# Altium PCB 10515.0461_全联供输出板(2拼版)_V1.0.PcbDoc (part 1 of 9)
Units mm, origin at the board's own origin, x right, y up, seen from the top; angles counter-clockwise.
Board outline 283.88 x 134.8 mm, 2 copper layers (Top Layer, Bottom Layer); 298 components, 0 nets, 1264 pads, 970 vias.
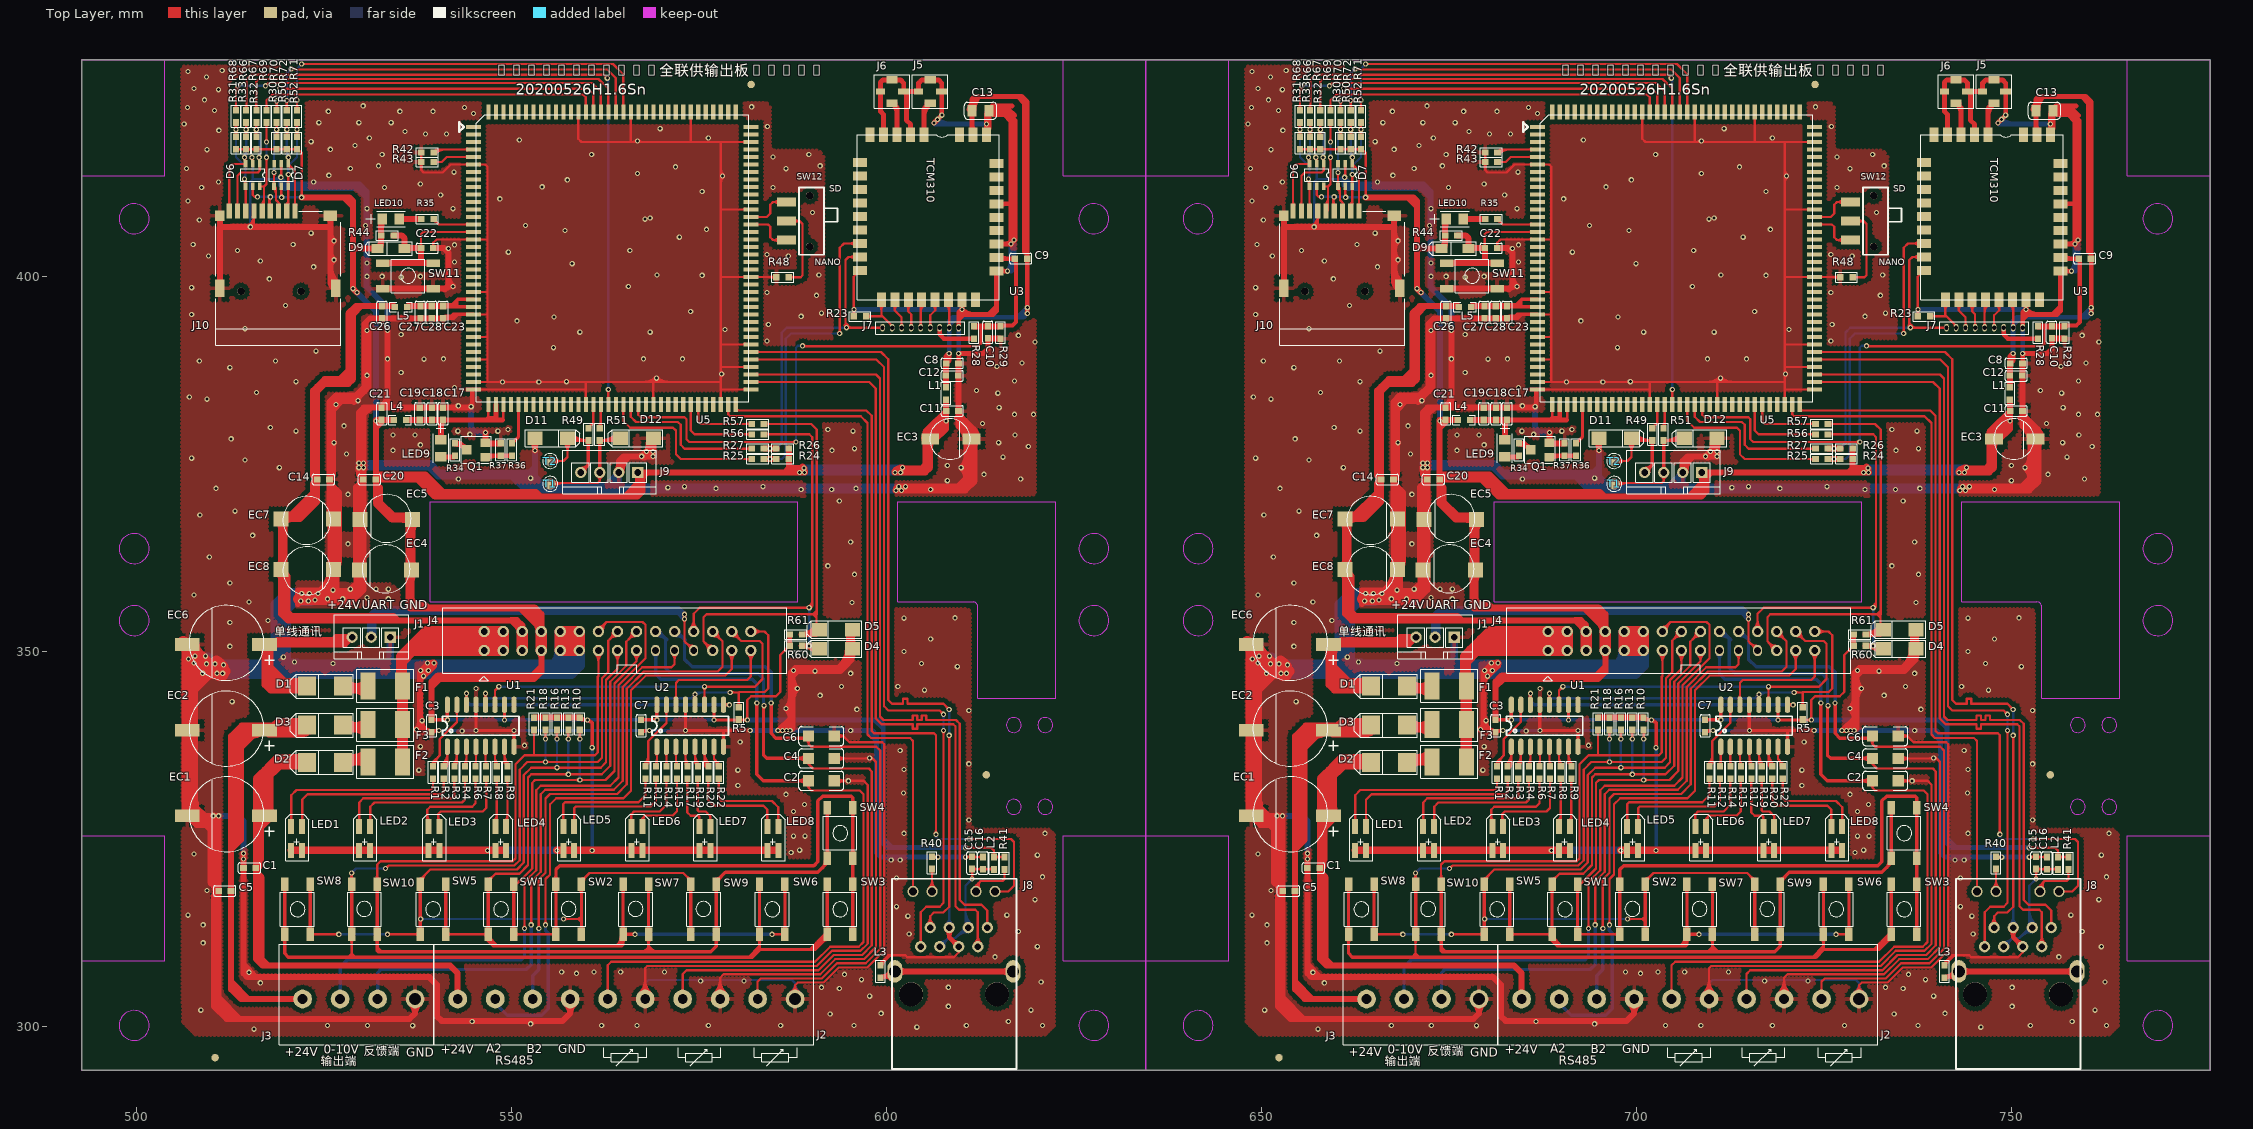
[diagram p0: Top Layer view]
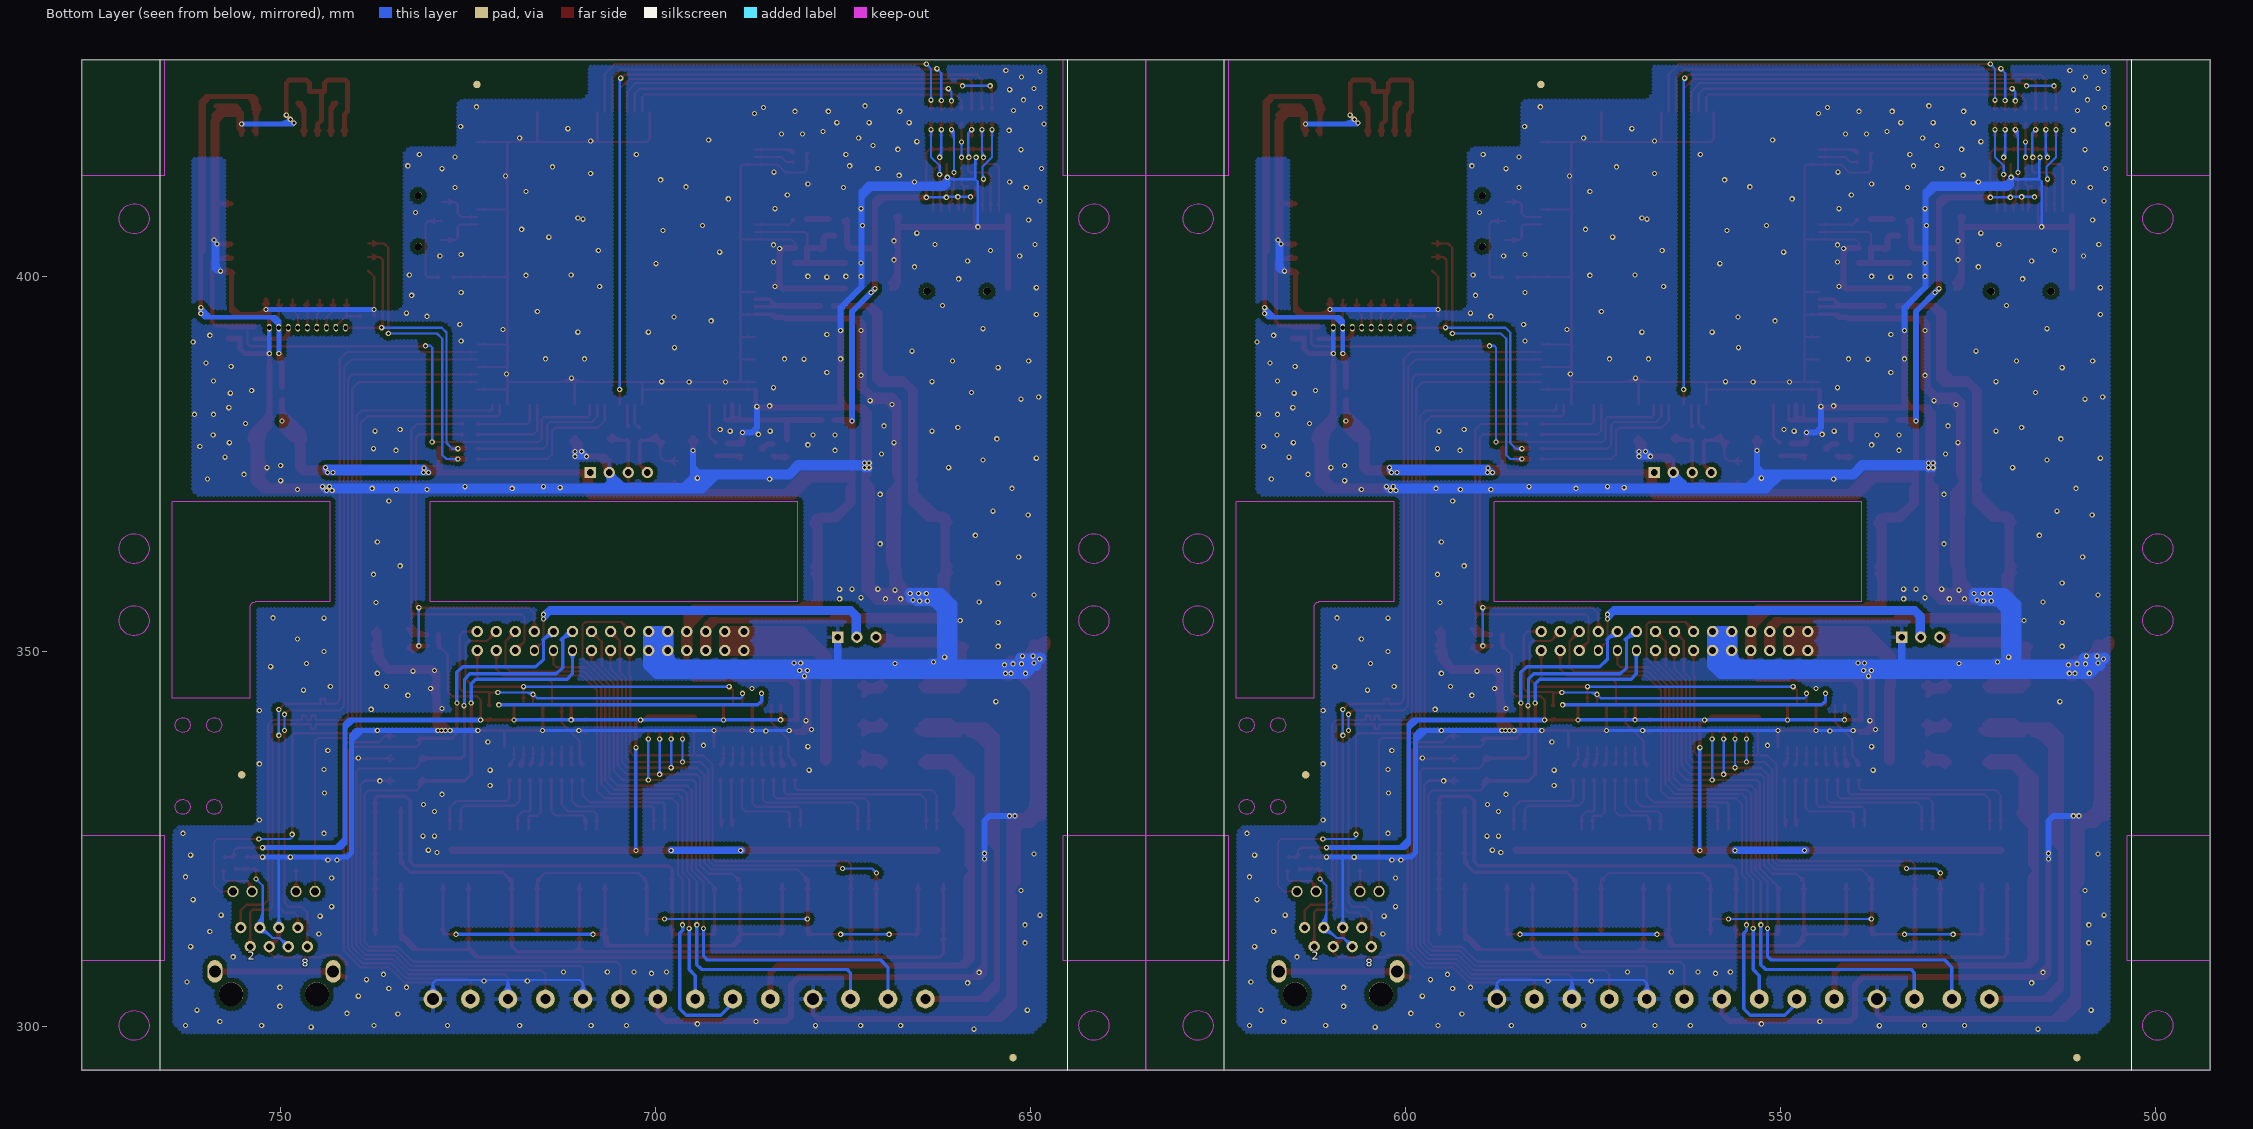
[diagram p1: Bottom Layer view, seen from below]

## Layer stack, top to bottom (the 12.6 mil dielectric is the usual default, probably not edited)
Top Layer: signal copper 0.0356
Dielectric: dielectric 0.32, FR-4, Dk 4.8
Bottom Layer: signal copper 0.0356

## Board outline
492.633,428.879 776.517,428.879 776.517,294.079 492.633,294.079 492.633,428.879

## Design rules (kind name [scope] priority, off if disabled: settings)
Clearance [All] p1: gap=0.254
PolygonConnect [All] p1: connectstyle=Relief reliefconductorwidth=0.254 reliefentries=4 polygonreliefangle="90 Angle"
RoutingVias [All] p1: holewidth=0.711 width=1.27 viastyle="Through Hole" minholewidth=0.711 minwidth=1.27 maxholewidth=0.711 maxwidth=1.27
SilkscreenOverComponentPads [All] p1: minsilkscreentomaskgap=0.254
SolderMaskExpansion [All] p1: expansion=0.102
Width [All] p1: maxlimit=0.254 minlimit=0.254 preferedwidth=0.254
27 further rules are at their usual default settings.

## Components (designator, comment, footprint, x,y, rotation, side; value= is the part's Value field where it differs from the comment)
C1 "0.1uF/0603" CAP/SMT/0603C 656.123,321.003 r0 top
C1 "0.1uF/0603" CAP/SMT/0603C 514.223,321.003 r0 top
C2 "1nF/1206" CAP/SMT/1206C 731.434,332.687 r0 top
C2 "1nF/1206" CAP/SMT/1206C 589.534,332.687 r0 top
C3 "0.1uF/0603" CAP/SMT/0603C 681.142,340.815 r270 top
C3 "0.1uF/0603" CAP/SMT/0603C 539.242,340.815 r270 top
C4 "1nF/1206" CAP/SMT/1206C 731.434,335.672 r0 top
C4 "1nF/1206" CAP/SMT/1206C 589.534,335.672 r0 top
C5 "0.1uF/0603" CAP/SMT/0603C 652.821,317.955 r0 top
C5 "0.1uF/0603" CAP/SMT/0603C 510.921,317.955 r0 top
C6 "1nF/1206" CAP/SMT/1206C 731.434,338.656 r0 top
C6 "1nF/1206" CAP/SMT/1206C 589.534,338.656 r0 top
C7 "0.1uF/0603" CAP/SMT/0603C 709.082,340.815 r270 top
C7 "0.1uF/0603" CAP/SMT/0603C 567.182,340.815 r270 top
C8 "10uF/0603" CAP/SMT/0603C 749.849,388.313 r0 top
C8 "10uF/0603" CAP/SMT/0603C 607.949,388.313 r0 top
C9 "0.1uF/0603" CAP/SMT/0603C 758.993,402.283 r0 top
C9 "0.1uF/0603" CAP/SMT/0603C 617.093,402.283 r0 top
C10 "0.1uF/0603" CAP/SMT/0603C 755.437,391.742 r90 top
C10 "0.1uF/0603" CAP/SMT/0603C 613.537,391.742 r90 top
C11 "0.1uF/0603" CAP/SMT/0603C 749.849,381.963 r0 top
C11 "0.1uF/0603" CAP/SMT/0603C 607.949,381.963 r0 top
C12 "0.1uF/0603" CAP/SMT/0603C 751.404,386.789 r180 top
C12 "0.1uF/0603" CAP/SMT/0603C 609.504,386.789 r180 top
C13 "22uF/0805" CAP/SMT/0805C 755.564,422.095 r180 top
C13 "22uF/0805" CAP/SMT/0805C 613.664,422.095 r180 top
C14 "0.1uF/0603" CAP/SMT/0603C 667.553,372.969 r180 top
C14 "0.1uF/0603" CAP/SMT/0603C 525.653,372.969 r180 top
C15 "0.1uF/0603" CAP/SMT/0603C 753.336,320.963 r90 top
C15 "0.1uF/0603" CAP/SMT/0603C 611.436,320.963 r90 top
C16 "10uF/0603" CAP/SMT/0603C 754.675,322.517 r270 top
C16 "10uF/0603" CAP/SMT/0603C 612.775,322.517 r270 top
C17 "1uF/0603" CAP/SMT/0603C 682.666,382.446 r270 top
C17 "1uF/0603" CAP/SMT/0603C 540.766,382.446 r270 top
C18 "0.1uF/0603" CAP/SMT/0603C 681.18,382.446 r270 top
C18 "0.1uF/0603" CAP/SMT/0603C 539.28,382.446 r270 top
C19 "0.1uF/0603" CAP/SMT/0603C 679.568,382.446 r270 top
C19 "0.1uF/0603" CAP/SMT/0603C 537.668,382.446 r270 top
C20 "1uF/0603" CAP/SMT/0603C 672.125,372.819 r0 top
C20 "1uF/0603" CAP/SMT/0603C 530.225,372.819 r0 top
C21 "0.1uF/0603" CAP/SMT/0603C 674.488,382.446 r270 top
C21 "0.1uF/0603" CAP/SMT/0603C 532.588,382.446 r270 top
C22 "0.1uF/0603" CAP/SMT/0603C 681.396,403.807 r180 top
C22 "0.1uF/0603" CAP/SMT/0603C 539.496,403.807 r180 top
C23 "0.1uF/0603" CAP/SMT/0603C 682.793,394.409 r90 top
C23 "0.1uF/0603" CAP/SMT/0603C 540.893,394.409 r90 top
C26 "0.1uF/0603" CAP/SMT/0603C 674.665,394.409 r90 top
C26 "0.1uF/0603" CAP/SMT/0603C 532.765,394.409 r90 top
C27 "0.1uF/0603" CAP/SMT/0603C 679.745,394.409 r90 top
C27 "0.1uF/0603" CAP/SMT/0603C 537.845,394.409 r90 top
C28 "0.1uF/0603" CAP/SMT/0603C 681.269,394.409 r90 top
C28 "0.1uF/0603" CAP/SMT/0603C 539.369,394.409 r90 top
D1 "1N5819" D/SMT/DO-214AC 669.331,345.387 r0 top
D1 "1N5819" D/SMT/DO-214AC 527.431,345.387 r0 top
D2 "1N5819" D/SMT/DO-214AC 669.331,335.227 r0 top
D2 "1N5819" D/SMT/DO-214AC 527.431,335.227 r0 top
D3 "1N5819" D/SMT/DO-214AC 669.331,340.18 r0 top
D3 "1N5819" D/SMT/DO-214AC 527.431,340.18 r0 top
D4 "SMF6.5CA/SOD-123" D/SMT/SOD123 732.704,350.34 r0 top
D4 "SMF6.5CA/SOD-123" D/SMT/SOD123 590.804,350.34 r0 top
D5 "SMF6.5CA/SOD-123" D/SMT/SOD123 732.704,352.88 r0 top
D5 "SMF6.5CA/SOD-123" D/SMT/SOD123 590.804,352.88 r0 top
D6 "SR05-4B/SOT-363" TSOT-6L 658.282,414.983 r270 top
D6 "SR05-4B/SOT-363" TSOT-6L 516.382,414.983 r270 top
D7 "SR05-4B/SOT-363" TSOT-6L 662.092,414.983 r270 top
D7 "SR05-4B/SOT-363" TSOT-6L 520.192,414.983 r270 top
D9 "1N4148/SOD-123" D/SMT/SOD-123 675.808,403.68 r0 top
D9 "1N4148/SOD-123" D/SMT/SOD-123 533.908,403.68 r0 top
D11 "SMF6.5CA/SOD-123" D/SMT/SOD123 699.557,378.407 r180 top
D11 "SMF6.5CA/SOD-123" D/SMT/SOD123 557.657,378.407 r180 top
D12 "SMF6.5CA/SOD-123" D/SMT/SOD123 706.161,378.407 r0 top
D12 "SMF6.5CA/SOD-123" D/SMT/SOD123 564.261,378.407 r0 top
EC1 "220uF/50V" CAP/SMT/220UF/50V 658.917,323.035 r180 top
EC1 "220uF/50V" CAP/SMT/220UF/50V 517.017,323.035 r180 top
EC2 "220uF/50V" CAP/SMT/220UF/50V 658.917,334.465 r180 top
EC2 "220uF/50V" CAP/SMT/220UF/50V 517.017,334.465 r180 top
EC3 "47uF/16V" CAP/SMT/47uF/16V 747.69,378.28 r0 top
EC3 "47uF/16V" CAP/SMT/47uF/16V 605.79,378.28 r0 top
EC4 "100uF/25V" CAP/SMT/100UF/25V 678.221,360.677 r180 top
EC4 "100uF/25V" CAP/SMT/100UF/25V 536.321,360.677 r180 top
EC5 "100uF/25V" CAP/SMT/100UF/25V 678.348,367.408 r180 top
EC5 "100uF/25V" CAP/SMT/100UF/25V 536.448,367.408 r180 top
EC6 "220uF/50V" CAP/SMT/220UF/50V 658.917,345.895 r180 top
EC6 "220uF/50V" CAP/SMT/220UF/50V 517.017,345.895 r180 top
EC7 "100uF/25V" CAP/SMT/100UF/25V 661.457,367.739 r0 top
EC7 "100uF/25V" CAP/SMT/100UF/25V 519.557,367.739 r0 top
EC8 "100uF/25V" CAP/SMT/100UF/25V 661.457,361.008 r0 top
EC8 "100uF/25V" CAP/SMT/100UF/25V 519.557,361.008 r0 top
F1 "500MA" FUSE/100MA/SMC 677.332,345.387 r180 top
F1 "500MA" FUSE/100MA/SMC 535.432,345.387 r180 top
F2 "500MA" FUSE/100MA/SMC 672.665,335.227 r0 top
F2 "500MA" FUSE/100MA/SMC 530.765,335.227 r0 top
F3 "500MA" FUSE/100MA/SMC 672.665,340.18 r0 top
F3 "500MA" FUSE/100MA/SMC 530.765,340.18 r0 top
J1 "CON/DIP/1X3PIN/2.54MM" CON/DIP/1×3PIN/2.54MM/插件端子 675.681,351.864 r270 top
J1 "CON/DIP/1X3PIN/2.54MM" CON/DIP/1×3PIN/2.54MM/插件端子 533.781,351.864 r270 top
J2 "WJ305-5.0" CON/DIP/1×10PIN/5.0MM/WJ103-10P 707.177,303.604 r180 top locked
J2 "WJ305-5.0" CON/DIP/1×10PIN/5.0MM/WJ103-10P 565.277,303.604 r180 top locked
J3 "WJ103-5.0" CON/DIP/1×4PIN/5.0MM/WJ103-4P 671.49,303.604 r180 top
J3 "WJ103-5.0" CON/DIP/1×4PIN/5.0MM/WJ103-4P 529.59,303.604 r180 top
J4 "CON/DIP/2X15PIN" CON/DIP/2X15PIN/2.54MM 688.206,350.086 r90 top
J4 "CON/DIP/2X15PIN" CON/DIP/2X15PIN/2.54MM 546.306,350.086 r90 top
J5 "NC" W.FL.LP-3MM 747.69,424.635 r270 top
J5 "NC" W.FL.LP-3MM 605.79,424.635 r270 top
J6 "Antena_W.FL-LP" W.FL.LP-3MM 742.61,424.635 r270 top
J6 "Antena_W.FL-LP" W.FL.LP-3MM 600.71,424.635 r270 top
J7 "CON/1X9PIN" CON/DIP/1×9PIN/1.27MM 751.5,393.139 r180 top
J7 "CON/1X9PIN" CON/DIP/1×9PIN/1.27MM 609.6,393.139 r180 top
J8 "MJ3A-B211-RSL15T022-1" RJ45-MJ3A-B211-RSL15T022-1 745.404,317.955 r0 top locked
J8 "MJ3A-B211-RSL15T022-1" RJ45-MJ3A-B211-RSL15T022-1 603.504,317.955 r0 top locked
J9 "1X4PIN/2.54MM" CON/DIP/1×4PIN/2.54MM/插件端子 708.701,373.835 r270 top
J9 "1X4PIN/2.54MM" CON/DIP/1×4PIN/2.54MM/插件端子 566.801,373.835 r270 top
J10 "OTHER/MicroSD" TF-01A 660.695,403.553 r0 top
J10 "OTHER/MicroSD" TF-01A 518.795,403.553 r0 top
L1 "10uH/0603/磁珠" 0603R 749.776,384.376 r90 top
L1 "10uH/0603/磁珠" 0603R 607.876,384.376 r90 top
L2 "220R/0603/磁珠" 0603R 756.199,321.715 r270 top
L2 "220R/0603/磁珠" 0603R 614.299,321.715 r270 top
L3 "10uH/0603/磁珠" 0603R 741.086,307.287 r270 top
L3 "10uH/0603/磁珠" 0603R 599.186,307.287 r270 top
L4 "L/10uH" L/SMT/0603L 676.189,380.878 r0 top
L4 "L/10uH" L/SMT/0603L 534.289,380.878 r0 top
L5 "L/10uH" L/SMT/0603L 676.316,395.933 r0 top
L5 "L/10uH" L/SMT/0603L 534.416,395.933 r0 top
LED1 "WEJT910C-R3H4共阳" D/SMT/WEJT910C-R3H4 662.473,323.416 r90 top
LED1 "WEJT910C-R3H4共阳" D/SMT/WEJT910C-R3H4 520.573,323.416 r90 top
LED2 "WEJT910C-R3H4共阳" D/SMT/WEJT910C-R3H4 671.544,323.416 r90 top
LED2 "WEJT910C-R3H4共阳" D/SMT/WEJT910C-R3H4 529.644,323.416 r90 top
LED3 "WEJT910C-R3H4共阳" D/SMT/WEJT910C-R3H4 680.761,323.416 r90 top
LED3 "WEJT910C-R3H4共阳" D/SMT/WEJT910C-R3H4 538.861,323.416 r90 top
LED4 "WEJT910C-R3H4共阳" D/SMT/WEJT910C-R3H4 689.687,323.416 r90 top
LED4 "WEJT910C-R3H4共阳" D/SMT/WEJT910C-R3H4 547.787,323.416 r90 top
LED5 "WEJT910C-R3H4共阳" D/SMT/WEJT910C-R3H4 698.759,323.416 r90 top
LED5 "WEJT910C-R3H4共阳" D/SMT/WEJT910C-R3H4 556.859,323.416 r90 top
LED6 "WEJT910C-R3H4共阳" D/SMT/WEJT910C-R3H4 707.83,323.416 r90 top
LED6 "WEJT910C-R3H4共阳" D/SMT/WEJT910C-R3H4 565.93,323.416 r90 top
LED7 "WEJT910C-R3H4共阳" D/SMT/WEJT910C-R3H4 716.902,323.416 r90 top
LED7 "WEJT910C-R3H4共阳" D/SMT/WEJT910C-R3H4 575.002,323.416 r90 top
LED8 "WEJT910C-R3H4共阳" D/SMT/WEJT910C-R3H4 725.973,323.416 r90 top
LED8 "WEJT910C-R3H4共阳" D/SMT/WEJT910C-R3H4 584.073,323.416 r90 top
LED9 "WEJT81GC-0805" D/SMT/LED/0805 682.285,375.867 r90 top
LED9 "WEJT81GC-0805" D/SMT/LED/0805 540.385,375.867 r90 top
LED10 "WEJT81GC-0805" D/SMT/LED/0805 676.951,407.49 r180 top
LED10 "WEJT81GC-0805" D/SMT/LED/0805 535.051,407.49 r180 top
Q1 "NPN_SS8050" BJT/SMT/SOT-23 688.381,375.867 r90 top
Q1 "NPN_SS8050" BJT/SMT/SOT-23 546.481,375.867 r90 top
R1 "1K/0603" 0603R 681.396,333.83 r270 top
R1 "1K/0603" 0603R 539.496,333.83 r270 top
R2 "1K/0603" 0603R 682.811,333.83 r270 top
R2 "1K/0603" 0603R 540.911,333.83 r270 top
R3 "1K/0603" 0603R 684.226,333.83 r270 top
R3 "1K/0603" 0603R 542.326,333.83 r270 top
R4 "1K/0603" 0603R 685.641,333.83 r270 top
R4 "1K/0603" 0603R 543.741,333.83 r270 top
R5 "10K/0603" 0603R 722.163,341.704 r90 top
R5 "10K/0603" 0603R 580.263,341.704 r90 top
R6 "1K/0603" 0603R 687.057,333.83 r270 top
R6 "1K/0603" 0603R 545.157,333.83 r270 top
R7 "1K/0603" 0603R 688.472,333.83 r270 top
R7 "1K/0603" 0603R 546.572,333.83 r270 top
R8 "1K/0603" 0603R 689.887,333.83 r270 top
R8 "1K/0603" 0603R 547.987,333.83 r270 top
R9 "1K/0603" 0603R 691.302,333.83 r270 top
R9 "1K/0603" 0603R 549.402,333.83 r270 top
R10 "10K/0603" 0603R 700.954,340.307 r90 top
R10 "10K/0603" 0603R 559.054,340.307 r90 top
R11 "1K/0603" 0603R 709.717,333.83 r270 top
R11 "1K/0603" 0603R 567.817,333.83 r270 top
R12 "1K/0603" 0603R 711.114,333.83 r270 top
R12 "1K/0603" 0603R 569.214,333.83 r270 top
R13 "10K/0603" 0603R 699.43,340.307 r90 top
R13 "10K/0603" 0603R 557.53,340.307 r90 top
R14 "1K/0603" 0603R 712.511,333.83 r270 top
R14 "1K/0603" 0603R 570.611,333.83 r270 top
R15 "1K/0603" 0603R 713.908,333.83 r270 top
R15 "1K/0603" 0603R 572.008,333.83 r270 top
R16 "10K/0603" 0603R 697.906,340.307 r90 top
R16 "10K/0603" 0603R 556.006,340.307 r90 top
R17 "1K/0603" 0603R 715.305,333.83 r270 top
R17 "1K/0603" 0603R 573.405,333.83 r270 top
R18 "10K/0603" 0603R 696.382,340.307 r90 top
R18 "10K/0603" 0603R 554.482,340.307 r90 top
R19 "1K/0603" 0603R 716.702,333.83 r270 top
R19 "1K/0603" 0603R 574.802,333.83 r270 top
R20 "1K/0603" 0603R 718.099,333.83 r270 top
R20 "1K/0603" 0603R 576.199,333.83 r270 top
R21 "10K/0603" 0603R 694.858,340.307 r90 top
R21 "10K/0603" 0603R 552.958,340.307 r90 top
R22 "1K/0603" 0603R 719.496,333.83 r270 top
R22 "1K/0603" 0603R 577.596,333.83 r270 top
R23 "10K/0603" 0603R 738.336,394.663 r0 top
R23 "10K/0603" 0603R 596.436,394.663 r0 top
R24 "10K/0603" 0603R 728.005,375.613 r0 top
R24 "10K/0603" 0603R 586.105,375.613 r0 top
R25 "100R/0603" 0603R 724.703,375.613 r0 top
R25 "100R/0603" 0603R 582.803,375.613 r0 top
R26 "10K/0603" 0603R 728.005,377.01 r0 top
R26 "10K/0603" 0603R 586.105,377.01 r0 top
R27 "100R/0603" 0603R 724.703,377.01 r0 top
R27 "100R/0603" 0603R 582.803,377.01 r0 top
R28 "100R/0603" 0603R 753.532,392.504 r90 top
R28 "100R/0603" 0603R 611.632,392.504 r90 top
R29 "10K/0603" 0603R 757.088,392.504 r90 top
R29 "10K/0603" 0603R 615.188,392.504 r90 top
R30 "10K/0603" 0603R 660.526,417.777 r270 top
R30 "10K/0603" 0603R 518.626,417.777 r270 top
R31 "10K/0603" 0603R 655.107,417.777 r270 top
R31 "10K/0603" 0603R 513.207,417.777 r270 top
R32 "10K/0603" 0603R 657.816,417.777 r270 top
R32 "10K/0603" 0603R 515.916,417.777 r270 top
R33 "10K/0603" 0603R 656.462,417.777 r270 top
R33 "10K/0603" 0603R 514.562,417.777 r270 top
R34 "1K/0603" 0603R 684.317,376.883 r90 top
R34 "1K/0603" 0603R 542.417,376.883 r90 top
R35 "1K/0603" 0603R 680.634,407.617 r180 top
R35 "1K/0603" 0603R 538.734,407.617 r180 top
R36 "4.7K/0603" 0603R 691.937,376.883 r270 top
R36 "4.7K/0603" 0603R 550.037,376.883 r270 top
R37 "10K/0603" 0603R 690.413,376.883 r270 top
R37 "10K/0603" 0603R 548.513,376.883 r270 top
R40 "470R/0603" 0603R 747.944,321.765 r90 top
R40 "470R/0603" 0603R 606.044,321.765 r90 top
R41 "470R/0603" 0603R 757.596,321.715 r90 top
R41 "470R/0603" 0603R 615.696,321.715 r90 top
R42 "1K/0603" 0603R 680.634,416.507 r180 top
R42 "1K/0603" 0603R 538.734,416.507 r180 top
R43 "NC 1K/0603" 0603R 680.634,415.237 r180 top
R43 "NC 1K/0603" 0603R 538.734,415.237 r180 top
R44 "10K/0603" 0603R 675.3,405.458 r180 top
R44 "10K/0603" 0603R 533.4,405.458 r180 top
R48 "1K/0603" 0603R 728.005,399.87 r0 top
R48 "1K/0603" 0603R 586.105,399.87 r0 top
R49 "100R/0603" 0603R 702.097,378.915 r90 top
R49 "100R/0603" 0603R 560.197,378.915 r90 top
R50 "10K/0603" 0603R 661.88,417.777 r270 top
R50 "10K/0603" 0603R 519.98,417.777 r270 top
R51 "100R/0603" 0603R 703.621,378.915 r90 top
R51 "100R/0603" 0603R 561.721,378.915 r90 top
R52 "10K/0603" 0603R 663.235,417.777 r270 top
R52 "10K/0603" 0603R 521.335,417.777 r270 top
R56 "100R/0603" 0603R 724.703,378.915 r0 top
R56 "100R/0603" 0603R 582.803,378.915 r0 top
R57 "100R/0603" 0603R 724.703,380.312 r0 top
R57 "100R/0603" 0603R 582.803,380.312 r0 top
R60 "10K/0603" 0603R 729.783,350.721 r180 top
R60 "10K/0603" 0603R 587.883,350.721 r180 top
R61 "10K/0603" 0603R 729.783,352.245 r180 top
R61 "10K/0603" 0603R 587.883,352.245 r180 top
R66 "22R/0603" 0603R 656.462,421.333 r270 top
R66 "22R/0603" 0603R 514.562,421.333 r270 top
R67 "22R/0603" 0603R 657.816,421.333 r270 top
R67 "22R/0603" 0603R 515.916,421.333 r270 top
R68 "22R/0603" 0603R 655.107,421.333 r270 top
R68 "22R/0603" 0603R 513.207,421.333 r270 top
R69 "22R/0603" 0603R 659.171,421.333 r270 top
R69 "22R/0603" 0603R 517.271,421.333 r270 top
R70 "22R/0603" 0603R 660.526,421.333 r270 top
R70 "22R/0603" 0603R 518.626,421.333 r270 top
R71 "22R/0603" 0603R 663.235,421.333 r270 top
R71 "22R/0603" 0603R 521.335,421.333 r270 top
R72 "22R/0603" 0603R 661.88,421.333 r270 top
R72 "22R/0603" 0603R 519.98,421.333 r270 top
SW1 "KAN4542-0381A" SWITCH/KAN4542 690.381,315.415 r90 top
SW1 "KAN4542-0381A" SWITCH/KAN4542 548.481,315.415 r90 top
SW2 "KAN4542-0381A" SWITCH/KAN4542 699.532,315.771 r270 top
SW2 "KAN4542-0381A" SWITCH/KAN4542 557.632,315.771 r270 top
SW3 "KAN4542-0381A" SWITCH/KAN4542 735.625,315.415 r90 top
SW3 "KAN4542-0381A" SWITCH/KAN4542 593.725,315.415 r90 top
SW4 "KAN4542-0381A" SWITCH/KAN4542 735.625,325.575 r90 top
SW4 "KAN4542-0381A" SWITCH/KAN4542 593.725,325.575 r90 top
SW5 "KAN4542-0381A" SWITCH/KAN4542 681.332,315.415 r90 top
SW5 "KAN4542-0381A" SWITCH/KAN4542 539.433,315.415 r90 top
SW6 "KAN4542-0381A" SWITCH/KAN4542 726.576,315.415 r90 top
SW6 "KAN4542-0381A" SWITCH/KAN4542 584.676,315.415 r90 top
SW7 "KAN4542-0381A" SWITCH/KAN4542 708.479,315.771 r270 top
SW7 "KAN4542-0381A" SWITCH/KAN4542 566.579,315.771 r270 top
SW8 "KAN4542-0381A" SWITCH/KAN4542 663.235,315.415 r90 top
SW8 "KAN4542-0381A" SWITCH/KAN4542 521.335,315.415 r90 top
SW9 "KAN4542-0381A" SWITCH/KAN4542 717.527,315.771 r270 top
SW9 "KAN4542-0381A" SWITCH/KAN4542 575.627,315.771 r270 top
SW10 "KAN4542-0381A" SWITCH/KAN4542 672.284,315.771 r270 top
SW10 "KAN4542-0381A" SWITCH/KAN4542 530.384,315.771 r270 top
SW11 "KAN4542-0381A" SWITCH/KAN4542 678.221,399.997 r180 top
SW11 "KAN4542-0381A" SWITCH/KAN4542 536.321,399.997 r180 top
SW12 "K3-1280S-F2" SWITCH/K3-1280S-F2 728.513,407.363 r270 top
SW12 "K3-1280S-F2" SWITCH/K3-1280S-F2 586.613,407.363 r270 top
T1 "TEST" TEST 697.017,372.311 r0 top
T1 "TEST" TEST 555.117,372.311 r0 top
T2 "TEST" TEST 697.017,375.359 r0 top
T2 "TEST" TEST 555.117,375.359 r0 top
U1 "SN74HC595" SOP-16 683.301,337.259 r90 top
U1 "SN74HC595" SOP-16 541.401,337.259 r90 top
U2 "SN74HC595" SOP-16 711.241,337.259 r90 top
U2 "SN74HC595" SOP-16 569.341,337.259 r90 top
U3 "TCM_310" TCM310 747.436,407.871 r270 top
U3 "TCM_310" TCM310 605.536,407.871 r270 top
U5 "MCU/SMT/MYCY6UL" MYC140 705.265,402.41 r270 top locked
U5 "MCU/SMT/MYCY6UL" MYC140 563.365,402.41 r270 top locked

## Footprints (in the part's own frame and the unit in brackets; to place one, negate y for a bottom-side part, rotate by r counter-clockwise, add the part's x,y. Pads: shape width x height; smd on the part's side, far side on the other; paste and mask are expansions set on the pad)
0603R [mil]
  rect 35x32 smd: 1(-32.5,0) 2(32.5,0)
  silkscreen extent -58,-25 58,25, body extent -33,-15 30,16, height 18
BJT/SMT/SOT-23 [mm] "transistor 1base 2emitter 3collector"
  rect 1.143x1.27 smd: 1(0,0) 2(1.95,0)
  rect 1.27x1.27 smd: 3(1,2.5)
  silkscreen extent -0.78,-0.8 2.78,3.26, body extent -0.38,-0.13 2.52,2.67, height 1.2
CAP/SMT/47uF/16V [mm]
  rect 2.4x1.5 smd: 1(0.01,0.017) 2(5.5,0.017)
  silkscreen extent -0.07,-2.7 5.33,2.7
CAP/SMT/100UF/25V [mm]
  rect 2x2 smd: 1(-0.325,-0.127) 2(6.675,-0.127)
  silkscreen extent -0.1,-3.49 6.29,2.91
CAP/SMT/220UF/50V [mm]
  rect 3.3x1.7 smd: 1(0,-5) 2(10.3,-5)
  silkscreen extent -1.27,-10.21 10.08,-0.21
CAP/SMT/0603C [mil]
  rect 35x32 smd: 1(-1,1.97) 2(64,1.97)
  silkscreen extent -28,-24 89,30, body extent -20,-20 82,19, height 35
CAP/SMT/0805C [mm]
  rect 1.2x1.524 smd: 1(0.01,0.01) 2(2.296,0.01)
  silkscreen extent -0.99,-1.13 3.32,1.15, body extent -0.38,-0.64 2.62,0.76, height 0.93
CAP/SMT/1206C [mm]
  rect 1.5x1.5 smd: 1(0.026,0.025) 2(3.455,0.025)
  silkscreen extent -1.25,-1.24 4.73,1.3, body extent -0.38,-0.89 3.82,0.91, height 0.95
CON/DIP/1×3PIN/2.54MM/插件端子 [mm]
  rect 1.5x1.5 hole 0.9: 1(0,0)
  round 1.5 hole 0.9: 2(0,-2.54) 3(0,-5.08)
  silkscreen extent -2.99,-7.5 2.86,2.46
CON/DIP/1×4PIN/2.54MM/插件端子 [mm]
  rect 1.5x1.5 hole 0.9: 1(0,0)
  round 1.5 hole 0.9: 2(0,-2.54) 3(0,-5.08) 4(0,-7.62)
  silkscreen extent -2.99,-10 2.86,2.46
CON/DIP/1×4PIN/5.0MM/WJ103-4P [mm]
  round 2.5 hole 1.6: 1(-7.5,0)
  round 2.5 hole 1.3: 2(-2.5,0) 3(2.5,0) 4(7.5,0)
  silkscreen extent -10,-7.3 10.6,6.1
CON/DIP/1×9PIN/1.27MM [mm]
  oval 0.6x1 hole 0.58: 1(0,0) 2(1.27,0) 3(2.54,0) 4(3.81,0) 5(5.08,0) 6(6.35,0) 7(7.62,0) 8(8.89,0) 9(10.16,0)
  silkscreen extent -0.81,-0.81 11.05,0.86
CON/DIP/1×10PIN/5.0MM/WJ103-10P [mm]
  round 2.5 hole 1.6: 1(-22.5,0)
  round 2.5 hole 1.3: 2(-17.5,0) 3(-12.5,0) 4(-7.5,0) 5(-2.5,0) 6(2.5,0) 7(7.5,0) 8(12.5,0) 9(17.5,0) 10(22.5,0)
  silkscreen extent -25,-7.3 25.63,6.1
CON/DIP/2X15PIN/2.54MM [mil]
  round 60 hole 35.43: 1(0,0) 2(100,0) 3(0,-100) 4(100,-100) 5(0,-200) 6(100,-200) 7(0,-300) 8(100,-300) 9(0,-400) 10(100,-400) 11(0,-500) 12(100,-500) 13(0,-600) 14(100,-600) 15(0,-700) 16(100,-700) 17(0,-800) 18(100,-800) 20(100,-900) 22(100,-1000) 24(100,-1100) 25(0,-1200) 26(100,-1200) 27(0,-1300) 28(100,-1300) 29(0,-1400) 30(100,-1400)
  oval 60x47.24 hole 35.43: 19(0,-900) 21(0,-1000) 23(0,-1100)
  silkscreen extent -158,-1588 225,218
D/SMT/DO-214AC [mil]
  rect 94.49x100 smd: 1(-187.98,-2) 2(1,-2)
  silkscreen extent -274,-65 56,61, body extent -190,-55 15,47, height 40
D/SMT/LED/0805 [mil]
  rect 50x60 smd: 1(2,-6) 2(92,-6)
  silkscreen extent -28,-46 178,34
D/SMT/SOD123 [mm]
  rect 2x1.8 smd: 1(0.229,0) 2(4.597,0)
  silkscreen extent -1.4,-1.14 5.84,1.14, body extent 0.51,-0.76 4.21,0.84, height 1.2
D/SMT/SOD-123 [mm]
  rect 1.6x1.2 smd: 1(-1.8,0) 2(1.8,0)
  silkscreen extent -3.43,-0.9 2.78,0.9, body extent -1.91,-0.76 1.79,0.84, height 1.2
D/SMT/WEJT910C-R3H4 [mm]
  rect 2x0.8 smd: 1(0,0) 2(3.2,0) 3(0,-1.46) 4(3.175,-1.46)
  silkscreen extent -1.4,-2.36 4.8,0.74
FUSE/100MA/SMC [mm]
  rect 2x3.6 smd: 1(0.033,0.018) 2(4.633,0.018)
  silkscreen extent -1.47,-2.18 6.13,2.22
L/SMT/0603L [mil]
  rect 35x32 smd: 1(-1,-1) 2(64,-1)
  silkscreen extent -28,-26 91,24
MYC140 [mm]
  rect 0.55x2 smd: 1(-17.5,-18.5) 2(-16.5,-18.5) 3(-15.5,-18.5) 4(-14.5,-18.5) 5(-13.5,-18.5) 6(-12.5,-18.5) 7(-11.5,-18.5) 8(-10.5,-18.5) 9(-9.5,-18.5) 10(-8.5,-18.5) 11(-7.5,-18.5) 12(-6.5,-18.5) 13(-5.5,-18.5) 14(-4.5,-18.5) 15(-3.5,-18.5) 16(-2.5,-18.5) 17(-1.5,-18.5) 18(-0.5,-18.5) 19(0.5,-18.5) 20(1.5,-18.5) 21(2.5,-18.5) 22(3.5,-18.5) 23(4.5,-18.5) 24(5.5,-18.5) 25(6.5,-18.5) 26(7.5,-18.5) 27(8.5,-18.5) 28(9.5,-18.5) 29(10.5,-18.5) 30(11.5,-18.5) 31(12.5,-18.5) 32(13.5,-18.5) 33(14.5,-18.5) 34(15.5,-18.5) 35(16.5,-18.5) 36(17.5,-18.5) 71(17.5,18.5) 72(16.5,18.5) 73(15.5,18.5) 74(14.5,18.5) 75(13.5,18.5) 76(12.5,18.5) 77(11.5,18.5) 78(10.5,18.5) 79(9.5,18.5) 80(8.5,18.5) 81(7.5,18.5) 82(6.5,18.5) 83(5.5,18.5) 84(4.5,18.5) 85(3.5,18.5) 86(2.5,18.5) 87(1.5,18.5) 88(0.5,18.5) 89(-0.5,18.5) 90(-1.5,18.5) 91(-2.5,18.5) 92(-3.5,18.5) 93(-4.5,18.5) 94(-5.5,18.5) 95(-6.5,18.5) 96(-7.5,18.5) 97(-8.5,18.5) 98(-9.5,18.5) 99(-10.5,18.5) 100(-11.5,18.5) 101(-12.5,18.5) 102(-13.5,18.5) 103(-14.5,18.5) 104(-15.5,18.5) 105(-16.5,18.5) 106(-17.5,18.5)
  rect 2x0.55 smd: 37(19.5,-16.5) 38(19.5,-15.5) 39(19.5,-14.5) 40(19.5,-13.5) 41(19.5,-12.5) 42(19.5,-11.5) 43(19.5,-10.5) 44(19.5,-9.5) 45(19.5,-8.5) 46(19.5,-7.5) 47(19.5,-6.5) 48(19.5,-5.5) 49(19.5,-4.5) 50(19.5,-3.5) 51(19.5,-2.5) 52(19.5,-1.5) 53(19.5,-0.5) 54(19.5,0.5) 55(19.5,1.5) 56(19.5,2.5) 57(19.5,3.5) 58(19.5,4.5) 59(19.5,5.5) 60(19.5,6.5) 61(19.5,7.5) 62(19.5,8.5) 63(19.5,9.5) 64(19.5,10.5) 65(19.5,11.5) 66(19.5,12.5) 67(19.5,13.5) 68(19.5,14.5) 69(19.5,15.5) 70(19.5,16.5) 107(-19.5,16.5) 108(-19.5,15.5) 109(-19.5,14.5) 110(-19.5,13.5) 111(-19.5,12.5) 112(-19.5,11.5) 113(-19.5,10.5) 114(-19.5,9.5) 115(-19.5,8.5) 116(-19.5,7.5) 117(-19.5,6.5) 118(-19.5,5.5) 119(-19.5,4.5) 120(-19.5,3.5) 121(-19.5,2.5) 122(-19.5,1.5) 123(-19.5,0.5) 124(-19.5,-0.5) 125(-19.5,-1.5) 126(-19.5,-2.5) 127(-19.5,-3.5) 128(-19.5,-4.5) 129(-19.5,-5.5) 130(-19.5,-6.5) 131(-19.5,-7.5) 132(-19.5,-8.5) 133(-19.5,-9.5) 134(-19.5,-10.5) 135(-19.5,-11.5) 136(-19.5,-12.5) 137(-19.5,-13.5) 138(-19.5,-14.5) 139(-19.5,-15.5) 140(-19.5,-16.5)
  silkscreen extent -19.11,-20.38 19.12,18.2
RJ45-MJ3A-B211-RSL15T022-1 [mm]
  round 3.2 hole 3.2: 0(-0.25,-13.72) 0(11.18,-13.72)
  round 1.5 hole 0.9: 1(9.91,-4.83) 2(8.64,-7.37) 3(7.37,-4.83) 4(6.1,-7.37) 5(4.83,-4.83) 6(3.56,-7.37) 7(2.29,-4.83) 8(1.02,-7.37)
  round 1.5 hole 1.05: 9(0,0) 10(2.54,0) 11(8.39,0) 12(10.93,0)
  oval 2x3 hole 1.6: BO1(-2.43,-10.67) BO2(13.36,-10.67)
  silkscreen extent -2.82,-23.69 13.82,1.69
SOP-16 [mm]
  oval 2.2x0.7 smd: 1(0,0) 2(0,-1.27) 3(0,-2.54) 4(0,-3.81) 5(0,-5.08) 6(0,-6.35) 7(0,-7.62) 8(0,-8.89) 9(5.588,-8.89) 10(5.588,-7.62) 11(5.588,-6.35) 12(5.588,-5.08) 13(5.588,-3.81) 14(5.588,-2.54) 15(5.588,-1.27) 16(5.588,0)
  silkscreen extent 1.52,-9.53 4.06,0.64
SWITCH/K3-1280S-F2 [mm]
  rect 1.2x2.54 smd: 1(-2.54,0) 2(0,0) 3(2.54,0)
  round 1 hole 1 unplated: ""(-3.403,3.103) ""(3.396,3.1)
  silkscreen extent -4.5,1.7 4.5,6.8
SWITCH/KAN4542 [mm]
  rect 1.8x1 smd: 1(-3.172,-1.751) 2(3.528,-1.751) 3(3.528,1.649) 4(-3.172,1.649)
  silkscreen extent -2.07,-2.3 2.43,2.2
TCM310 [mm]
  rect 1.9x1.2 smd: 1(-11,7.75) 2(-11,5.95) 3(-11,4.15) 4(-11,-0.55) 5(-11,-2.35) 6(-11,-4.15) 7(-11,-5.95) 8(-11,-7.75) 18(11,-6.25) 19(11,-4.457) 20(11,-2.664) 21(11,-0.871) 22(11,0.921) 23(11,2.714) 24(11,4.507) 25(11,6.3)
  rect 1.2x1.9 smd: 9(-7.3,-9.1) 10(-5.5,-9.1) 11(-3.7,-9.1) 12(-1.9,-9.1) 13(-0.1,-9.1) 14(1.7,-9.1) 15(3.5,-9.1) 16(5.3,-9.1) 17(7.1,-9.1) 26(7.2,9.1) 27(5.4,9.1) 28(3.6,9.1) 29(1.8,9.1) 30(0,9.1) 31(-1.8,9.1) 32(-3.6,9.1) 33(-5.4,9.1) 34(-7.2,9.1)
  silkscreen extent -11,-9.5 11,9.5
TEST [mm]
  round 1.5 smd: 1(0,0)
  silkscreen extent -1,-1 1,1
TF-01A [mm]
  rect 0.7x2 smd: 1(2.292,5.145) 2(1.192,5.143) 3(0.096,5.145) 4(-1.004,5.145) 5(-2.103,5.145) 6(-3.201,5.145) 7(-4.297,5.145) 8(-5.395,5.145) 9(-6.499,5.145)
  rect 1.27x1.397 smd: 10(-7.747,4.507)
  rect 1.27x2.286 smd: 11(-7.747,-5.145) 12(7.747,-5.145)
  rect 1.778x1.397 smd: 13(6.985,4.507)
  round 1 hole 1 unplated: ""(-4.915,-5.557) ""(3.084,-5.554)
  silkscreen extent -8.31,-12.76 8.39,5.14
TSOT-6L [mm]
  rect 1x0.5 smd: 1(0,0) 2(0,-0.95) 3(0,-1.9) 4(3,-1.905) 5(3,-0.95) 6(3,0)
  silkscreen extent 0.63,-2.54 2.29,0.64
W.FL.LP-3MM [mm]
  rect 1x1.5 smd: 1(1.55,0) 2(-1.55,0)
  rect 0.8x1.5 smd: 3(0,1.55)
  rect 0.8x1.2 smd: 4(0,-1.55)
  silkscreen extent -2.24,-2.36 2.24,2.34

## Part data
C1 C1 C2 C2 C3 C3 C4 C4 C5 C5 C6 C6 C7 C7 C8 C8 C9 C9 C10 C10 C11 C11 C12 C12 C14 C14 C15 C15 C16 C16 C17 C17 C18 C18 C19 C19 C20 C20 C21 C21 C22 C22 C23 C23 C26 C26 C27 C27 C28 C28: library part CAP/CAP/SMT/0603C
C13 C13: library part CAP/CAP/SMT/0805C
D1 D1: library part D/D/SMT/1N4007/DO-214
D2 D2 D3 D3: library part D/D/SMT/1N5819/DO-214
D4 D4 D5 D5 D11 D11 D12 D12: library part D/TVS/SMT/SMF13CA/SOD-123
D6 D6 D7 D7: library part D/TVS/SMT/SR05-4B/SOT-363
D9 D9: library part D/D/SMT/1N4148/SOD-123, "VR=75V T(-65-175)P(0.5W)VF=0.6V"
EC1 EC1 EC2 EC2 EC6 EC6: library part CAP/AEC/DIP/330uF/25V
EC3 EC3: library part CAP/AEC/SMT/47uF/16V
EC4 EC4 EC5 EC5 EC7 EC7 EC8 EC8: library part CAP/AEC/SMT/100uF/25V
F1 F1 F2 F2 F3 F3: library part FUSE/PTC/SMT/100MA
J1 J1 J4 J4: "Connector"
J2 J2: library part CON/DIP/1X10PIN/WJ305-5.0, "Connector"
J3 J3: library part CON/DIP/1X4PIN/WJ103-5.0MM, "Connector"
J5 J5 J6 J6: library part Antena
J7 J7: library part CON/DIP/1X9PIN/1.27MM
J8 J8: library part RJ45B-48F-01GY2DPL2NL, "RJ45 + MAG"
J9 J9: library part CON/DIP/1X4PIN/2.54MM, "Connector"
L1 L1 L2 L2 L3 L3: library part INDUCTOR1
L4 L4 L5 L5: library part L/BEAD/SMT/0603L
LED1 LED1 LED2 LED2 LED3 LED3 LED4 LED4 LED5 LED5 LED6 LED6 LED7 LED7 LED8 LED8: library part D/LED/DIP/WEJT910C-R3H4-BA共阳
LED9 LED9 LED10 LED10: library part D/LED/SMT/BL-HUF35A-TRB高亮红/0805
Q1 Q1: library part BJT/NPN/SMT/SS8050/SOT-23
R1 R1 R2 R2 R3 R3 R4 R4 R5 R5 R6 R6 R7 R7 R8 R8 R9 R9 R10 R10 R11 R11 R12 R12 R13 R13 R14 R14 R15 R15 R16 R16 R17 R17 R18 R18 R19 R19 R20 R20 R21 R21 R22 R22 R23 R23 R24 R24 R25 R25 R26 R26 R27 R27 R28 R28 R29 R29 R30 R30 R31 R31 R32 R32 R33 R33 R40 R40 R41 R41 R42 R42 R43 R43 R44 R44 R49 R49 R50 R50 R51 R51 R52 R52 R56 R56 R57 R57 R60 R60 R61 R61 R66 R66 R67 R67 R68 R68 R69 R69 R70 R70 R71 R71 R72 R72: library part RES/RES/SMT/0603
R34 R34 R35 R35 R36 R36 R37 R37 R48 R48: library part Res, "Resistor"
SW1 SW1 SW2 SW2 SW3 SW3 SW4 SW4 SW5 SW5 SW6 SW6 SW7 SW7 SW8 SW8 SW9 SW9 SW10 SW10 SW11 SW11: library part SWITCH/TACT/SMT/KAN4542-0381A, "4.5mm*4.5mm*3.8mm"
SW12 SW12: library part SWITCH/DIP/K3-1280S-F2
U1 U1 U2 U2: library part IC/TTL/SMT/SN74HC595, "8-bit serial-in,serial or parallel-out shift register with output latches;3-state"

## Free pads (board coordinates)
  round 2 on Top Solder: 0(510.413,295.783) 0(581.914,425.577) 0(613.283,333.502) 0(652.313,295.783) 0(723.814,425.577) 0(755.183,333.502)
  round 1 all layers, no hole: 0(510.413,295.783) 0(581.914,425.577) 0(613.283,333.502) 0(652.313,295.783) 0(723.814,425.577) 0(755.183,333.502)
  round 2 on Bottom Solder: 0(510.413,295.783) 0(581.914,425.577) 0(613.283,333.502) 0(652.313,295.783) 0(723.814,425.577) 0(755.183,333.502)

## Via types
v1: diameter 0.7, hole 0.4, Top Layer to Bottom Layer, tented both sides, 970 vias

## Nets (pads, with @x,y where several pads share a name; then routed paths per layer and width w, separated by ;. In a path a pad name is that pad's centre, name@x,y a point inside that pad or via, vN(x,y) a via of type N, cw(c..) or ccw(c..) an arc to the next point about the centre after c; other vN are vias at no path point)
pads on no net: C1.1 C1.2 C2.1 C2.2 C3.1 C3.2 C4.1 C4.2 C5.1 C5.2 C6.1 C6.2 C7.1 C7.2 C8.1 C8.2 C9.1 C9.2 C10.1 C10.2 C11.1 C11.2 C12.1 C12.2 C13.1 C13.2 C14.1 C14.2 C15.1 C15.2 C16.1 C16.2 C17.1 C17.2 C18.1 C18.2 C19.1 C19.2 C20.1 C20.2 C21.1 C21.2 C22.1 C22.2 C23.1 C23.2 C26.1 C26.2 C27.1 C27.2 C28.1 C28.2 D1.1 D1.2 D2.1 D2.2 D3.1 D3.2 D4.1 D4.2 D5.1 D5.2 D6.1 D6.2 D6.3 D6.4 D6.5 D6.6 D7.1 D7.2 D7.3 D7.4 D7.5 D7.6 D9.1 D9.2 D11.1 D11.2 D12.1 D12.2 EC1.1 EC1.2 EC2.1 EC2.2 EC3.1 EC3.2 EC4.1 EC4.2 EC5.1 EC5.2 EC6.1 EC6.2 EC7.1 EC7.2 EC8.1 EC8.2 F1.1 F1.2 F2.1 F2.2 F3.1 F3.2 J1.1 J1.2 J1.3 J2.1 J2.2 J2.3 J2.4 J2.5 J2.6 J2.7 J2.8 J2.9 J2.10 J3.1 J3.2 J3.3 J3.4 J4.1 J4.2 J4.3 J4.4 J4.5 J4.6 J4.7 J4.8 J4.9 J4.10 J4.11 J4.12 J4.13 J4.14 J4.15 J4.16 J4.17 J4.18 J4.19 J4.20 J4.21 J4.22 J4.23 J4.24 J4.25 J4.26 J4.27 J4.28 J4.29 J4.30 J5.1 J5.2 J5.3 J5.4 J6.1 J6.2 J6.3 J6.4 J7.1 J7.2 J7.3 J7.4 J7.5 J7.6 J7.7 J7.8 J7.9 J8.0 J8.1 J8.2 J8.3 J8.4 J8.5 J8.6 J8.7 J8.8 J8.9 J8.10 J8.11 J8.12 J8.BO1 J8.BO2 J9.1 J9.2 J9.3 J9.4 J10. J10.1 J10.2 J10.3 J10.4 J10.5 J10.6 J10.7 J10.8 J10.9 J10.10 J10.11 J10.12 J10.13 L1.1 L1.2 L2.1 L2.2 L3.1 L3.2 L4.1 L4.2 L5.1 L5.2 LED1.1 LED1.2 LED1.3 LED1.4 LED2.1 LED2.2 LED2.3 LED2.4 LED3.1 LED3.2 LED3.3 LED3.4 LED4.1 LED4.2 LED4.3 LED4.4 LED5.1 LED5.2 LED5.3 LED5.4 LED6.1 LED6.2 LED6.3 LED6.4 LED7.1 LED7.2 LED7.3 LED7.4 LED8.1 LED8.2 LED8.3 LED8.4 LED9.1 LED9.2 LED10.1 LED10.2 Q1.1 Q1.2 Q1.3 R1.1 R1.2 R2.1 R2.2 R3.1 R3.2 R4.1 R4.2 R5.1 R5.2 R6.1 R6.2 R7.1 R7.2 R8.1 R8.2 R9.1 R9.2 R10.1 R10.2 R11.1 R11.2 R12.1 R12.2 R13.1 R13.2 R14.1 R14.2 R15.1 R15.2 R16.1 R16.2 R17.1 R17.2 R18.1 R18.2 R19.1 R19.2 R20.1 R20.2 R21.1 R21.2 R22.1 R22.2 R23.1 R23.2 R24.1 R24.2 R25.1 R25.2 R26.1 R26.2 R27.1 R27.2 R28.1 R28.2 R29.1 R29.2 R30.1 R30.2 R31.1 R31.2 R32.1 R32.2 R33.1 R33.2 R34.1 R34.2 R35.1 R35.2 R36.1 R36.2 R37.1 R37.2 R40.1 R40.2 R41.1 R41.2 R42.1 R42.2 R43.1 R43.2 R44.1 R44.2 R48.1 R48.2 R49.1 R49.2 R50.1 R50.2 R51.1 R51.2 R52.1 R52.2 R56.1 R56.2 R57.1 R57.2 R60.1 R60.2 R61.1 R61.2 R66.1 R66.2 R67.1 R67.2 R68.1 R68.2 R69.1 R69.2 R70.1 R70.2 R71.1 R71.2 R72.1 R72.2 SW1.1 SW1.2 SW1.3 SW1.4 SW2.1 SW2.2 SW2.3 SW2.4 SW3.1 SW3.2 SW3.3 SW3.4 SW4.1 SW4.2 SW4.3 SW4.4 SW5.1 SW5.2 SW5.3 SW5.4 SW6.1 SW6.2 SW6.3 SW6.4 SW7.1 SW7.2 SW7.3 SW7.4 SW8.1 SW8.2 SW8.3 SW8.4 SW9.1 SW9.2 SW9.3 SW9.4 SW10.1 SW10.2 SW10.3 SW10.4 SW11.1 SW11.2 SW11.3 SW11.4 SW12. SW12.1 SW12.2 SW12.3 T1.1 T2.1 U1.1 U1.2 U1.3 U1.4 U1.5 U1.6 U1.7 U1.8 U1.9 U1.10 U1.11 U1.12 U1.13 U1.14 U1.15 U1.16 U2.1 U2.2 U2.3 U2.4 U2.5 U2.6 U2.7 U2.8 U2.9 U2.10 U2.11 U2.12 U2.13 U2.14 U2.15 U2.16 U3.1 U3.2 U3.3 U3.4 U3.5 U3.6 U3.7 U3.8 U3.9 U3.10 U3.11 U3.12 U3.13 U3.14 U3.15 U3.16 U3.17 U3.18 U3.19 U3.20 U3.21 U3.22 U3.23 U3.24 U3.25 U3.26 U3.27 U3.28 U3.29 U3.30 U3.31 U3.32 U3.33 U3.34 U5.1 U5.2 U5.3 U5.4 U5.5 U5.6 U5.7 U5.8 U5.9 U5.10 U5.11 U5.12 U5.13 U5.14 U5.15 U5.16 U5.17 U5.18 U5.19 U5.20 U5.21 U5.22 U5.23 U5.24 U5.25 U5.26 U5.27 U5.28 U5.29 U5.30 U5.31 U5.32 U5.33 U5.34 U5.35 U5.36 U5.37 U5.38 U5.39 U5.40 U5.41 U5.42 U5.43 U5.44 U5.45 U5.46 U5.47 U5.48 U5.49 U5.50 U5.51 U5.52 U5.53 U5.54 U5.55 U5.56 U5.57 U5.58 U5.59 U5.60 U5.61 U5.62 U5.63 U5.64 U5.65 U5.66 U5.67 U5.68 U5.69 U5.70 U5.71 U5.72 U5.73 U5.74 U5.75 U5.76 U5.77 U5.78 U5.79 U5.80 U5.81 U5.82 U5.83 U5.84 U5.85 U5.86 U5.87 U5.88 U5.89 U5.90 U5.91 U5.92 U5.93 U5.94 U5.95 U5.96 U5.97 U5.98 U5.99 U5.100 U5.101 U5.102 U5.103 U5.104 U5.105 U5.106 U5.107 U5.108 U5.109 U5.110 U5.111 U5.112 U5.113 U5.114 U5.115 U5.116 U5.117 U5.118 U5.119 U5.120 U5.121 U5.122 U5.123 U5.124 U5.125 U5.126 U5.127 U5.128 U5.129 U5.130 U5.131 U5.132 U5.133 U5.134 U5.135 U5.136 U5.137 U5.138 U5.139 U5.140
copper on no net: | length 16184.1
